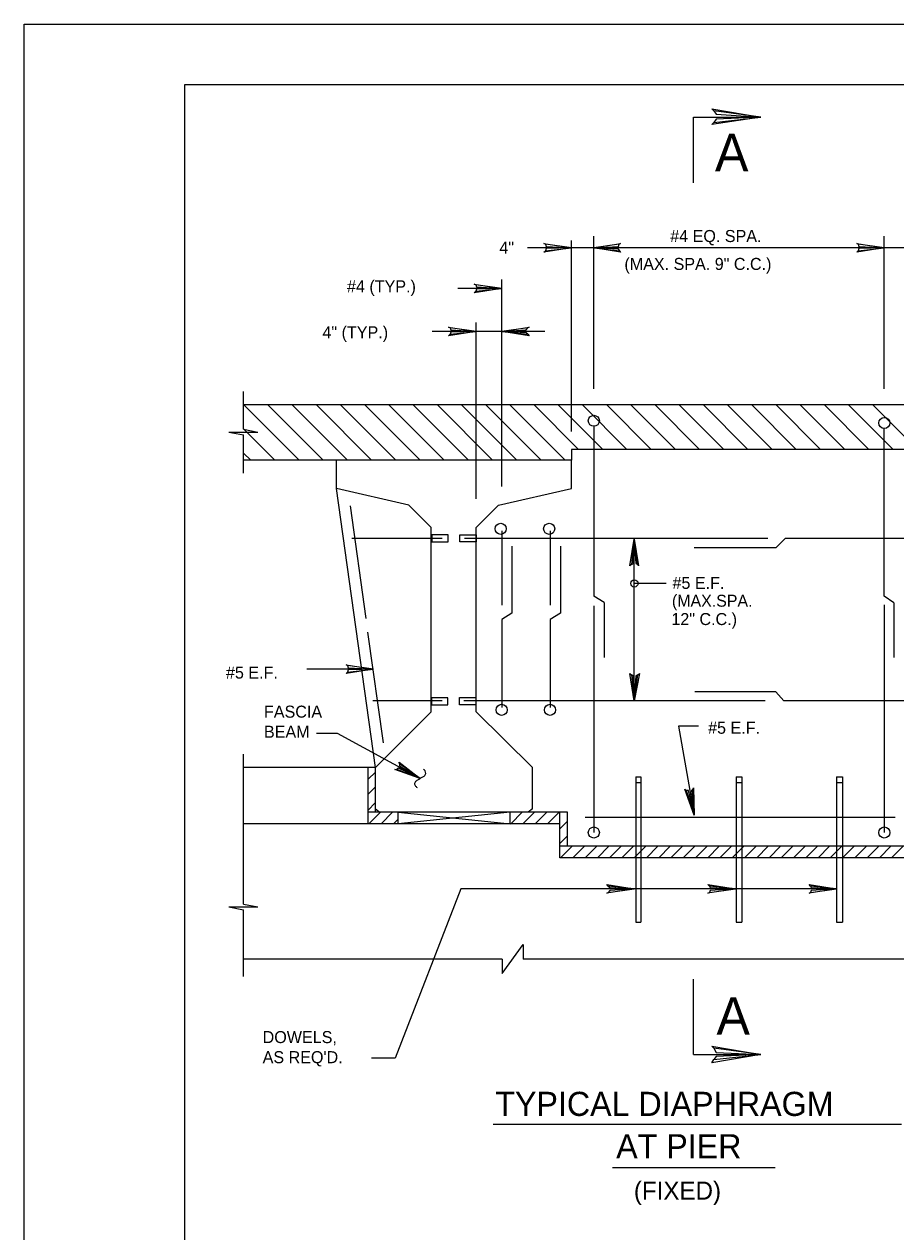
# Model space of a CAD drawing. Extents: x 639980 to 641204, y 298038 to 300414.
# Drawn here: x 639980.3 to 640197.5, y 300113 to 300413.8 of the extents above; entities that cross this region are included whole.
import ezdxf

# ---------------------------------------------------------------- set-up
doc = ezdxf.new("R2010")
doc.units = 0
doc.layers.add('2', color=7, linetype='Continuous')
doc.layers.add('PLT-BNDY', color=7, linetype='Continuous')

msp = doc.modelspace()

# ---------------------------------------------------------------- linework, layer by layer
at = {"layer": '2'}
for p, q in [((640020.31, 299834.78), (640020.31, 300398.78)), ((640020.31, 300398.78), (640806.31, 300398.78)), ((640147.08, 300374.27), (640147.08, 300390.62)), ((640147.08, 300390.62), (640163.82, 300390.62)), ((640116.66, 300312.37), (640116.66, 300359.89)), ((640122.24, 300322.99), (640122.24, 300360.97)), ((640194.6, 300322.99), (640194.6, 300360.97)), ((640116.66, 300358.09), (640105.7, 300358.09)), ((640200.18, 300358.09), (640116.66, 300358.09)), ((640099.3, 300298.65), (640099.3, 300350.22)), ((640099.3, 300347.99), (640088.33, 300347.99)), ((640092.9, 300295.53), (640092.9, 300339.5)), ((640099.3, 300337.27), (640081.94, 300337.27)), ((640110.02, 300337.27), (640099.3, 300337.27)), ((640034.94, 300312.91), (640034.94, 300322.27)), ((640034.94, 300319.03), (640281.9, 300319.03)), ((640034.94, 300319.03), (640034.94, 300319.03)), ((640034.94, 300319.03), (640034.94, 300319.03)), ((640034.94, 300319.03), (640048.8, 300305.17)), ((640040.97, 300319.03), (640054.83, 300305.17)), ((640047, 300319.03), (640060.86, 300305.17)), ((640053.03, 300319.03), (640066.89, 300305.17)), ((640059.06, 300319.03), (640072.92, 300305.17)), ((640065.08, 300319.03), (640078.94, 300305.17)), ((640071.11, 300319.03), (640084.97, 300305.17)), ((640077.14, 300319.03), (640091, 300305.17)), ((640083.17, 300319.03), (640097.03, 300305.17)), ((640089.2, 300319.03), (640103.06, 300305.17)), ((640095.22, 300319.03), (640109.08, 300305.17)), ((640101.25, 300319.03), (640115.11, 300305.17)), ((640107.28, 300319.03), (640118.44, 300307.87)), ((640113.31, 300319.03), (640124.47, 300307.87)), ((640119.34, 300319.03), (640130.5, 300307.87)), ((640125.36, 300319.03), (640136.52, 300307.87)), ((640131.39, 300319.03), (640142.55, 300307.87)), ((640137.42, 300319.03), (640148.58, 300307.87)), ((640143.45, 300319.03), (640154.61, 300307.87)), ((640149.48, 300319.03), (640160.64, 300307.87)), ((640155.5, 300319.03), (640166.66, 300307.87)), ((640161.53, 300319.03), (640172.69, 300307.87)), ((640167.56, 300319.03), (640178.72, 300307.87)), ((640173.59, 300319.03), (640184.75, 300307.87)), ((640179.62, 300319.03), (640190.78, 300307.87)), ((640185.64, 300319.03), (640196.8, 300307.87)), ((640191.67, 300319.03), (640205.53, 300305.17)), ((640031.34, 300312.19), (640038.54, 300312.19)), ((640031.34, 300312.19), (640034.94, 300311.47)), ((640034.94, 300313), (640042.78, 300305.17)), ((640034.94, 300312.91), (640038.54, 300312.19)), ((640034.94, 300301.93), (640034.94, 300311.47)), ((640122.24, 300313.63), (640122.24, 300271.33)), ((640194.6, 300271.33), (640194.6, 300313.09)), ((640034.94, 300306.98), (640036.75, 300305.17)), ((640116.66, 300305.17), (640034.94, 300305.17)), ((640058.16, 300305.17), (640058.16, 300305.17)), ((640058.16, 300298.15), (640058.16, 300305.17)), ((640200.18, 300307.87), (640116.66, 300307.87)), ((640116.66, 300307.87), (640116.66, 300305.17)), ((640116.66, 300305.17), (640116.66, 300305.17)), ((640116.66, 300298.15), (640116.66, 300305.17)), ((640076.16, 300294.01), (640058.16, 300298.15)), ((640067.88, 300228.67), (640058.16, 300298.15)), ((640098.48, 300294.01), (640116.66, 300298.15)), ((640065.54, 300265.75), (640061.58, 300293.83)), ((640081.74, 300288.43), (640076.16, 300294.01)), ((640092.9, 300288.43), (640098.48, 300294.01)), ((640081.74, 300242.53), (640081.74, 300288.43)), ((640092.9, 300242.53), (640092.9, 300288.43)), ((640099.3, 300287.6), (640099.3, 300269.08)), ((640111.37, 300287.6), (640111.37, 300269.08)), ((640084.44, 300285.73), (640061.94, 300285.73)), ((640165.62, 300285.73), (640090.02, 300285.73)), ((640132.32, 300245.23), (640132.32, 300285.55)), ((640169.94, 300285.73), (640167.57, 300283.38)), ((640226.28, 300285.73), (640169.94, 300285.73)), ((640101.83, 300283.81), (640101.83, 300267.11)), ((640113.91, 300283.81), (640113.91, 300267.11)), ((640167.57, 300283.38), (640147.26, 300283.38)), ((640132.27, 300274.53), (640140.26, 300274.53)), ((640124.78, 300269.72), (640122.24, 300271.33)), ((640122.24, 300268.94), (640122.24, 300212.47)), ((640124.78, 300269.72), (640124.78, 300256.03)), ((640196.96, 300269.71), (640194.6, 300271.33)), ((640194.6, 300269.18), (640194.6, 300212.47)), ((640196.96, 300269.71), (640196.96, 300256.03)), ((640101.83, 300267.11), (640099.3, 300265.51)), ((640113.91, 300267.11), (640111.37, 300265.51)), ((640099.3, 300265.51), (640099.3, 300243.63)), ((640111.37, 300265.51), (640111.37, 300243.63)), ((640069.86, 300234.79), (640065.9, 300262.33)), ((640067.34, 300253.15), (640050.75, 300253.15)), ((640084.44, 300245.23), (640067.16, 300245.23)), ((640164.93, 300245.23), (640089.84, 300245.23)), ((640167.58, 300247.51), (640147.44, 300247.51)), ((640169.58, 300245.23), (640167.58, 300247.51)), ((640226.64, 300245.23), (640169.58, 300245.23)), ((640067.88, 300228.67), (640081.74, 300242.53)), ((640092.9, 300242.53), (640106.94, 300228.67)), ((640148.34, 300238.95), (640143.3, 300238.95)), ((640143.3, 300238.95), (640147.26, 300216.79)), ((640058.35, 300237.14), (640053.12, 300237.14)), ((640079, 300225.89), (640058.35, 300237.14)), ((640034.94, 300194.65), (640034.94, 300232.01)), ((640067.88, 300228.67), (640034.94, 300228.67)), ((640066.01, 300214.63), (640066.01, 300228.67)), ((640066.01, 300225.73), (640067.82, 300227.54)), ((640067.88, 300217.51), (640067.88, 300228.67)), ((640106.94, 300218.41), (640106.94, 300228.67)), ((640066.01, 300222.02), (640067.78, 300223.79)), ((640132.68, 300226.33), (640132.68, 300190.15)), ((640132.68, 300226.33), (640133.94, 300226.33)), ((640132.68, 300224.89), (640133.94, 300224.89)), ((640133.94, 300226.33), (640133.94, 300190.15)), ((640157.7, 300226.33), (640157.7, 300190.15)), ((640157.7, 300226.33), (640159.14, 300226.33)), ((640157.7, 300224.89), (640159.14, 300224.89)), ((640159.14, 300226.33), (640159.14, 300190.15)), ((640182.72, 300226.33), (640182.72, 300190.15)), ((640182.72, 300226.33), (640184.16, 300226.33)), ((640182.72, 300224.89), (640184.16, 300224.89)), ((640184.16, 300226.33), (640184.16, 300190.15)), ((640066.01, 300218.07), (640067.78, 300219.84)), ((640067.88, 300218.41), (640068.96, 300217.51)), ((640106.94, 300218.41), (640105.86, 300217.51)), ((640105.86, 300217.51), (640066.01, 300217.51)), ((640066.01, 300217.51), (640066.01, 300217.51)), ((640066.19, 300214.63), (640069.07, 300217.51)), ((640069.24, 300214.63), (640072.12, 300217.51)), ((640072.3, 300214.63), (640073.46, 300215.8)), ((640073.46, 300214.63), (640073.46, 300217.51)), ((640073.46, 300217.51), (640101.36, 300214.63)), ((640101.36, 300217.51), (640073.46, 300214.63)), ((640101.36, 300214.63), (640101.36, 300217.51)), ((640101.36, 300217.51), (640101.36, 300217.51)), ((640101.54, 300214.63), (640104.42, 300217.51)), ((640104.59, 300214.63), (640107.47, 300217.51)), ((640115.66, 300217.51), (640105.86, 300217.51)), ((640107.65, 300214.63), (640110.53, 300217.51)), ((640110.7, 300214.63), (640113.58, 300217.51)), ((640113.69, 300213.33), (640115.51, 300215.14)), ((640113.78, 300206.17), (640113.78, 300217.51)), ((640115.66, 300209.05), (640115.66, 300217.51)), ((640115.66, 300217.51), (640115.66, 300217.51)), ((640197.28, 300216.25), (640120.08, 300216.25)), ((640113.78, 300214.63), (640034.94, 300214.63)), ((640113.76, 300214.63), (640113.78, 300214.66)), ((640113.77, 300209.77), (640115.59, 300211.59)), ((640203.06, 300209.05), (640113.78, 300209.05)), ((640113.78, 300209.05), (640113.78, 300209.05)), ((640113.96, 300206.17), (640116.84, 300209.05)), ((640117.01, 300206.17), (640119.89, 300209.05)), ((640120.07, 300206.17), (640122.95, 300209.05)), ((640123.12, 300206.17), (640126, 300209.05)), ((640126.18, 300206.17), (640129.06, 300209.05)), ((640129.23, 300206.17), (640132.11, 300209.05)), ((640132.29, 300206.17), (640135.17, 300209.05)), ((640135.34, 300206.17), (640138.22, 300209.05)), ((640138.4, 300206.17), (640141.28, 300209.05)), ((640141.45, 300206.17), (640144.33, 300209.05)), ((640144.51, 300206.17), (640147.39, 300209.05)), ((640147.56, 300206.17), (640150.44, 300209.05)), ((640150.62, 300206.17), (640153.5, 300209.05)), ((640153.67, 300206.17), (640156.55, 300209.05)), ((640156.72, 300206.17), (640159.6, 300209.05)), ((640159.78, 300206.17), (640162.66, 300209.05)), ((640162.83, 300206.17), (640165.71, 300209.05)), ((640165.89, 300206.17), (640168.77, 300209.05)), ((640168.94, 300206.17), (640171.82, 300209.05)), ((640172, 300206.17), (640174.88, 300209.05)), ((640175.05, 300206.17), (640177.93, 300209.05)), ((640178.11, 300206.17), (640180.99, 300209.05)), ((640181.16, 300206.17), (640184.04, 300209.05)), ((640184.22, 300206.17), (640187.1, 300209.05)), ((640187.27, 300206.17), (640190.15, 300209.05)), ((640190.33, 300206.17), (640193.21, 300209.05)), ((640193.38, 300206.17), (640196.26, 300209.05)), ((640196.44, 300206.17), (640199.32, 300209.05)), ((640203.06, 300206.17), (640113.78, 300206.17)), ((640089.11, 300198.43), (640072.74, 300156.31)), ((640132.32, 300198.43), (640089.11, 300198.43)), ((640157.52, 300198.43), (640132.32, 300198.43)), ((640182.72, 300198.43), (640157.52, 300198.43)), ((640031.34, 300193.93), (640038.54, 300193.93)), ((640031.34, 300193.93), (640034.94, 300193.21)), ((640034.94, 300194.65), (640038.54, 300193.93)), ((640034.94, 300176.65), (640034.94, 300193.21)), ((640132.68, 300190.15), (640133.94, 300190.15)), ((640157.7, 300190.15), (640159.14, 300190.15)), ((640182.72, 300190.15), (640184.16, 300190.15)), ((640099.38, 300177.37), (640104.6, 300184.57)), ((640104.6, 300184.57), (640104.6, 300180.97)), ((640099.38, 300180.97), (640034.94, 300180.97)), ((640099.38, 300180.97), (640099.38, 300177.37)), ((640213.14, 300180.97), (640104.6, 300180.97)), ((640147.08, 300157.21), (640147.08, 300175.93)), ((640072.74, 300156.31), (640066.82, 300156.31)), ((640147.08, 300157.21), (640163.82, 300157.21)), ((640097.16, 300139.83), (640198.91, 300139.83)), ((640126.89, 300129.02), (640167.39, 300129.02))]:
    msp.add_line(p, q, dxfattribs=at)
for points in [[(640152.16, 300392.18), (640152.68, 300391.4), (640163.82, 300390.62), (640152.16, 300392.18), (640151.64, 300392.7), (640163.82, 300390.62), (640152.68, 300390.11), (640152.16, 300389.33), (640163.82, 300390.62), (640151.64, 300388.81), (640152.16, 300389.33)], [(640110.18, 300358.99), (640110.36, 300358.45), (640116.66, 300358.09), (640110.18, 300358.99), (640109.82, 300359.17), (640116.66, 300358.09), (640110.36, 300357.91), (640110.18, 300357.37), (640116.66, 300358.09), (640109.82, 300357.01), (640110.18, 300357.37)], [(640128.72, 300357.37), (640128.36, 300357.73), (640122.24, 300358.09), (640128.72, 300357.37), (640128.9, 300357.01), (640122.24, 300358.09), (640128.36, 300358.45), (640128.54, 300358.99), (640122.24, 300358.09), (640128.9, 300359.17), (640128.54, 300358.99)], [(640188.12, 300358.99), (640188.3, 300358.45), (640194.6, 300358.09), (640188.12, 300358.99), (640187.76, 300359.17), (640194.6, 300358.09), (640188.3, 300357.91), (640188.12, 300357.37), (640194.6, 300358.09), (640187.76, 300357.01), (640188.12, 300357.37)], [(640092.82, 300348.89), (640093, 300348.35), (640099.3, 300347.99), (640092.82, 300348.89), (640092.46, 300349.07), (640099.3, 300347.99), (640093, 300347.81), (640092.82, 300347.27), (640099.3, 300347.99), (640092.46, 300346.91), (640092.82, 300347.27)], [(640086.42, 300338.17), (640086.6, 300337.63), (640092.9, 300337.27), (640086.42, 300338.17), (640086.06, 300338.35), (640092.9, 300337.27), (640086.6, 300337.09), (640086.42, 300336.55), (640092.9, 300337.27), (640086.06, 300336.19), (640086.42, 300336.55)], [(640105.78, 300336.55), (640105.42, 300336.91), (640099.3, 300337.27), (640105.78, 300336.55), (640106.14, 300336.19), (640099.3, 300337.27), (640105.42, 300337.63), (640105.78, 300338.17), (640099.3, 300337.27), (640106.14, 300338.35), (640105.78, 300338.17)], [(640131.6, 300279.25), (640132.14, 300279.43), (640132.32, 300285.55), (640131.6, 300279.25), (640131.24, 300278.89), (640132.32, 300285.55), (640132.68, 300279.43), (640133.22, 300279.25), (640132.32, 300285.55), (640133.4, 300278.89), (640133.22, 300279.25)], [(640060.86, 300254.05), (640061.04, 300253.51), (640067.34, 300253.15), (640060.86, 300254.05), (640060.5, 300254.23), (640067.34, 300253.15), (640061.04, 300252.97), (640060.86, 300252.43), (640067.34, 300253.15), (640060.5, 300252.07), (640060.86, 300252.43)], [(640133.22, 300251.71), (640132.68, 300251.53), (640132.32, 300245.23), (640133.22, 300251.71), (640133.58, 300252.07), (640132.32, 300245.23), (640132.14, 300251.53), (640131.6, 300251.71), (640132.32, 300245.23), (640131.24, 300252.07), (640131.6, 300251.71)], [(640073.86, 300229.59), (640073.85, 300229.07), (640079, 300225.89), (640073.86, 300229.59), (640073.71, 300229.98), (640079, 300225.89), (640073.55, 300228.52), (640073.14, 300228.23), (640079, 300225.89), (640072.7, 300228.13), (640073.14, 300228.23)], [(640146.9, 300223.27), (640146.54, 300222.91), (640147.26, 300216.79), (640146.9, 300223.27), (640147.08, 300223.63), (640147.26, 300216.79), (640145.82, 300222.91), (640145.28, 300222.91), (640147.26, 300216.79), (640144.92, 300223.27), (640145.28, 300222.91)], [(640125.84, 300199.15), (640126.2, 300198.79), (640132.32, 300198.43), (640125.84, 300199.15), (640125.48, 300199.51), (640132.32, 300198.43), (640126.2, 300198.07), (640125.84, 300197.53), (640132.32, 300198.43), (640125.48, 300197.35), (640125.84, 300197.53)], [(640151.04, 300199.15), (640151.22, 300198.79), (640157.52, 300198.43), (640151.04, 300199.15), (640150.68, 300199.51), (640157.52, 300198.43), (640151.22, 300198.07), (640151.04, 300197.53), (640157.52, 300198.43), (640150.68, 300197.35), (640151.04, 300197.53)], [(640176.24, 300199.15), (640176.42, 300198.79), (640182.72, 300198.43), (640176.24, 300199.15), (640175.88, 300199.51), (640182.72, 300198.43), (640176.42, 300198.07), (640176.24, 300197.53), (640182.72, 300198.43), (640175.88, 300197.35), (640176.24, 300197.53)], [(640152.16, 300158.77), (640152.68, 300157.73), (640163.82, 300157.21), (640152.16, 300158.77), (640151.64, 300159.29), (640163.82, 300157.21), (640152.68, 300156.69), (640152.16, 300155.92), (640163.82, 300157.21), (640151.64, 300155.14), (640152.16, 300155.92)]]:
    msp.add_lwpolyline(points, dxfattribs=at)
for points in [[(640081.86, 300284.83), (640085.92, 300284.83), (640085.92, 300286.62), (640081.86, 300286.62)], [(640092.93, 300284.86), (640088.87, 300284.86), (640088.87, 300286.64), (640092.93, 300286.64)], [(640081.82, 300244.26), (640085.88, 300244.26), (640085.88, 300246.04), (640081.82, 300246.04)], [(640092.86, 300244.29), (640088.8, 300244.29), (640088.8, 300246.08), (640092.86, 300246.08)]]:
    msp.add_lwpolyline(points, close=True, dxfattribs=at)
for centre, radius in [((640122.24, 300315.01), 1.38), ((640194.6, 300314.47), 1.38), ((640099.04, 300288.11), 1.38), ((640111.12, 300288.11), 1.38), ((640132.34, 300274.52), 0.908), ((640099.27, 300243.02), 1.38), ((640111.34, 300243.02), 1.38), ((640122.24, 300212.47), 1.38), ((640194.6, 300212.47), 1.38)]:
    msp.add_circle(centre, radius, dxfattribs=at)
msp.add_spline([(640078.31, 300223.6), (640077.8, 300224.11), (640077.67, 300224.75), (640078.05, 300225.38), (640078.69, 300225.77), (640079.33, 300226.15), (640079.96, 300226.53), (640080.35, 300227.17), (640080.22, 300227.8), (640079.84, 300228.18)], degree=3, dxfattribs=at)
at = {"layer": 'PLT-BNDY'}
msp.add_lwpolyline([(639980.31, 300413.78), (640821.31, 300413.78), (640821.31, 299819.78), (639980.31, 299819.78)], close=True, dxfattribs=at)

# ---------------------------------------------------------------- texts
at = {"layer": '2'}
for s, height, p in [('A', 9.33, (640152.43, 300377.16)), ('#4 EQ. SPA. ', 2.9987, (640141.28, 300359.52)), ('4"', 2.999, (640098.7, 300356.62)), ('(MAX. SPA. 9" C.C.)', 2.9987, (640129.86, 300352.57)), ('#4 (TYP.)', 2.999, (640060.75, 300346.98)), ('4" (TYP.)', 2.999, (640054.63, 300335.54)), ('#5 E.F.', 2.999, (640141.84, 300273.14)), ('(MAX.SPA.', 2.969, (640141.7, 300268.71)), ('12" C.C.)', 2.999, (640141.56, 300264.13)), ('#5 E.F.', 2.999, (640030.59, 300250.81)), ('FASCIA', 2.999, (640040.06, 300241.07)), ('BEAM', 2.999, (640040.06, 300236.07)), ('#5 E.F.', 2.999, (640150.71, 300237.07)), ('A', 9.33, (640152.8, 300162.14)), ('DOWELS,', 2.999, (640039.73, 300160.03)), ("AS REQ'D.", 2.999, (640039.73, 300155.03)), ('TYPICAL DIAPHRAGM', 6, (640097.69, 300141.9)), ('AT PIER', 6, (640127.81, 300131.35)), ('(FIXED)', 4.5, (640132.21, 300121.05))]:
    msp.add_text(s, height=height, dxfattribs=at).set_placement(p)

doc.saveas('drawing.dxf')
